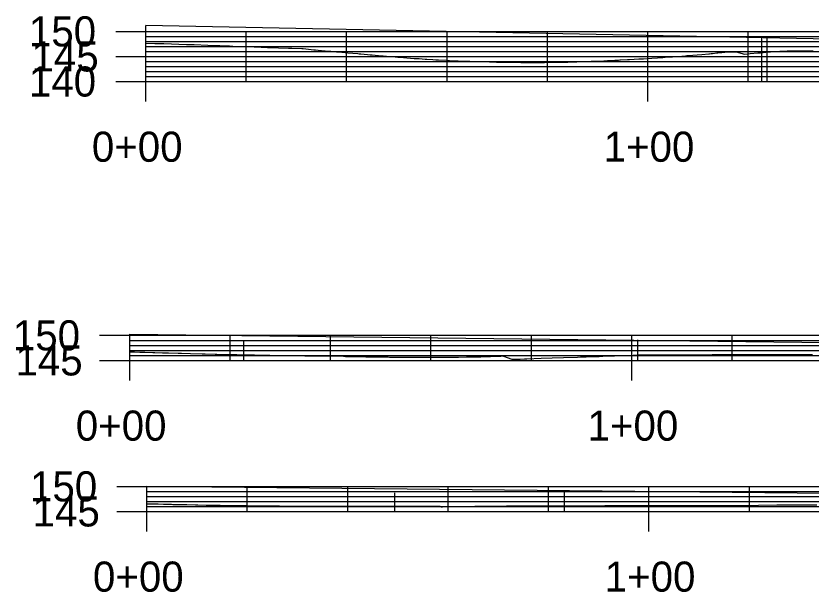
# Model space of a CAD drawing. Extents: x 1556849 to 1559393, y 1802592 to 1804749.
# Drawn here: x 1559135.3 to 1559293.7, y 1802770.9 to 1802885.8 of the extents above; entities that cross this region are included whole.
import ezdxf

# ---------------------------------------------------------------- set-up
doc = ezdxf.new("R2010")
doc.units = 0
for name, color, linetype in [('R_Axis', 7, 'Continuous'), ('R_Axis Annot', 7, 'Continuous'), ('R_Fin Surface', 7, 'Continuous'), ('R_Grid', 7, 'Continuous'), ('R_Proposed Const Limits_Hand', 7, 'Continuous'), ('R_Vert Alg Annot', 7, 'Continuous')]:
    doc.layers.add(name, color=color, linetype=linetype)

msp = doc.modelspace()

# ---------------------------------------------------------------- linework, layer by layer
at = {"layer": 'R_Axis'}
for p, q in [((1559161.2, 1802872.74), (1559161.2, 1802882.74)), ((1559161.2, 1802872.74), (1559361.2, 1802872.74)), ((1559158, 1802817.13), (1559158, 1802822.13)), ((1559158, 1802817.13), (1559358, 1802817.13)), ((1559161.42, 1802787.02), (1559161.42, 1802792.02)), ((1559161.42, 1802787.02), (1559361.42, 1802787.02))]:
    msp.add_line(p, q, dxfattribs=at)
at = {"layer": 'R_Fin Surface'}
for points in [[(1559161.2, 1802880.39), (1559163.01, 1802880.33), (1559164.76, 1802880.29), (1559169.29, 1802880.15), (1559170.23, 1802880.12), (1559170.8, 1802880.1), (1559173.55, 1802880.01), (1559175.33, 1802879.95), (1559175.37, 1802879.95), (1559175.67, 1802879.93), (1559175.96, 1802879.92), (1559177.86, 1802879.85), (1559178.53, 1802879.82), (1559180.34, 1802879.75), (1559180.47, 1802879.74), (1559180.68, 1802879.74), (1559181.6, 1802879.7), (1559182.79, 1802879.65), (1559184.18, 1802879.6), (1559185.22, 1802879.56), (1559185.43, 1802879.55), (1559185.55, 1802879.55), (1559187.04, 1802879.49), (1559187.61, 1802879.47), (1559189.64, 1802879.4), (1559189.98, 1802879.38), (1559190.27, 1802879.37), (1559190.31, 1802879.37), (1559192.3, 1802879.3), (1559192.32, 1802879.3), (1559192.53, 1802879.3), (1559194.64, 1802879.08), (1559194.7, 1802879.08), (1559194.97, 1802879.05), (1559195.51, 1802879), (1559196.93, 1802878.87), (1559198.03, 1802878.77), (1559199.21, 1802878.66), (1559199.41, 1802878.64), (1559199.54, 1802878.63), (1559200.89, 1802878.51), (1559201.46, 1802878.46), (1559203.43, 1802878.3), (1559203.7, 1802878.27), (1559204.01, 1802878.25), (1559204.03, 1802878.25), (1559205.35, 1802878.14), (1559205.92, 1802878.09), (1559206.29, 1802878.05), (1559208.13, 1802877.88), (1559208.3, 1802877.87), (1559208.46, 1802877.85), (1559209.89, 1802877.73), (1559210.32, 1802877.7), (1559211.39, 1802877.61), (1559212.5, 1802877.52), (1559212.55, 1802877.52), (1559212.84, 1802877.5), (1559213.22, 1802877.47), (1559214.67, 1802877.36), (1559215.63, 1802877.3), (1559216.83, 1802877.22), (1559217.02, 1802877.21), (1559217.17, 1802877.2), (1559218.38, 1802877.13), (1559218.98, 1802877.09), (1559219.51, 1802877.06), (1559221.12, 1802876.97), (1559221.18, 1802876.97), (1559221.47, 1802876.96), (1559221.7, 1802876.95), (1559223.26, 1802876.87), (1559223.39, 1802876.87), (1559225.39, 1802876.78), (1559225.39, 1802876.78), (1559225.58, 1802876.78), (1559225.74, 1802876.77), (1559225.74, 1802876.77), (1559226.9, 1802876.74), (1559227.53, 1802876.73), (1559229.65, 1802876.67), (1559229.66, 1802876.67), (1559230.01, 1802876.66), (1559230.29, 1802876.65), (1559231.07, 1802876.63), (1559231.07, 1802876.63), (1559231.77, 1802876.62), (1559231.77, 1802876.62), (1559231.95, 1802876.61), (1559233.85, 1802876.58), (1559233.89, 1802876.58), (1559234.24, 1802876.57), (1559234.25, 1802876.57), (1559235.91, 1802876.55), (1559236.01, 1802876.55), (1559237.92, 1802876.54), (1559238.14, 1802876.54), (1559238.47, 1802876.54), (1559238.51, 1802876.54), (1559239.42, 1802876.54), (1559239.57, 1802876.54), (1559239.67, 1802876.54), (1559240.27, 1802876.54), (1559240.62, 1802876.55), (1559242.4, 1802876.57), (1559242.49, 1802876.57), (1559242.77, 1802876.58), (1559243.22, 1802876.59), (1559244.54, 1802876.61), (1559245.23, 1802876.63), (1559246.68, 1802876.67), (1559246.83, 1802876.67), (1559247.06, 1802876.68), (1559247.81, 1802876.7), (1559248.83, 1802876.73), (1559249.91, 1802876.77), (1559250.99, 1802876.82), (1559251.21, 1802876.82), (1559251.38, 1802876.83), (1559252.45, 1802876.88), (1559253.16, 1802876.91), (1559254.65, 1802876.98), (1559255.34, 1802877.01), (1559255.63, 1802877.03), (1559255.74, 1802877.03), (1559257.14, 1802877.11), (1559257.53, 1802877.13), (1559259.43, 1802877.23), (1559259.74, 1802877.25), (1559260.11, 1802877.27), (1559260.15, 1802877.28), (1559260.35, 1802877.29), (1559261.96, 1802877.39), (1559263.11, 1802877.47), (1559264.05, 1802877.53), (1559264.2, 1802877.54), (1559264.58, 1802877.57), (1559264.62, 1802877.57), (1559266.08, 1802877.68), (1559266.45, 1802877.7), (1559267.96, 1802877.82), (1559268.73, 1802877.88), (1559268.99, 1802877.9), (1559269.17, 1802877.92), (1559270.13, 1802878), (1559271.02, 1802878.07), (1559271.94, 1802878.15), (1559273.34, 1802878.28), (1559273.48, 1802878.29), (1559273.8, 1802878.32), (1559274.1, 1802878.35), (1559274.97, 1802878.43), (1559275.11, 1802878.44), (1559275.68, 1802878.5), (1559275.96, 1802878.53), (1559277.23, 1802878.67), (1559277.23, 1802878.67), (1559277.23, 1802878.67), (1559277.94, 1802878.68), (1559278.05, 1802878.68), (1559278.29, 1802878.68), (1559278.81, 1802878.69), (1559280.44, 1802878.2), (1559281.59, 1802878.3), (1559283.1, 1802878.43), (1559283.27, 1802878.44), (1559283.63, 1802878.47), (1559284.73, 1802878.57), (1559287.51, 1802878.81), (1559288.27, 1802878.82), (1559288.96, 1802878.83), (1559291.04, 1802878.86), (1559293.32, 1802878.89), (1559294.14, 1802878.89)], [(1559158, 1802818.86), (1559158.93, 1802818.83), (1559159.99, 1802818.8), (1559161.03, 1802818.77), (1559162.57, 1802818.73), (1559162.7, 1802818.72), (1559162.97, 1802818.71), (1559164.53, 1802818.67), (1559165.11, 1802818.65), (1559165.69, 1802818.64), (1559167.62, 1802818.58), (1559167.96, 1802818.57), (1559168.02, 1802818.57), (1559168.31, 1802818.57), (1559170.11, 1802818.52), (1559172.45, 1802818.46), (1559172.57, 1802818.45), (1559172.57, 1802818.45), (1559172.97, 1802818.44), (1559173.02, 1802818.44), (1559175, 1802818.39), (1559175.34, 1802818.38), (1559177.41, 1802818.33), (1559177.51, 1802818.33), (1559177.81, 1802818.32), (1559178.15, 1802818.31), (1559179.09, 1802818.29), (1559179.32, 1802818.28), (1559179.8, 1802818.27), (1559180.71, 1802818.25), (1559182.17, 1802818.22), (1559182.35, 1802818.22), (1559182.56, 1802818.21), (1559182.71, 1802818.21), (1559182.87, 1802818.21), (1559183.3, 1802818.2), (1559183.74, 1802818.19), (1559184.15, 1802818.19), (1559184.52, 1802818.18), (1559185.93, 1802818.16), (1559186.85, 1802818.14), (1559187.11, 1802818.14), (1559187.24, 1802818.14), (1559188.61, 1802818.12), (1559189.16, 1802818.11), (1559191, 1802818.09), (1559191.46, 1802818.08), (1559191.79, 1802818.08), (1559191.86, 1802818.08), (1559192.85, 1802818.07), (1559193.01, 1802818.07), (1559193.67, 1802818.06), (1559193.75, 1802818.06), (1559193.98, 1802818.06), (1559196.03, 1802818.04), (1559196.04, 1802818.04), (1559196.43, 1802818.04), (1559196.49, 1802818.04), (1559197.79, 1802818.03), (1559198.29, 1802818.02), (1559198.35, 1802818.01), (1559200.55, 1802817.95), (1559200.59, 1802817.95), (1559200.95, 1802817.94), (1559201.23, 1802817.94), (1559202.79, 1802817.9), (1559203.35, 1802817.89), (1559205.04, 1802817.86), (1559205.16, 1802817.86), (1559205.44, 1802817.85), (1559206.13, 1802817.84), (1559207.27, 1802817.83), (1559208.36, 1802817.82), (1559209.5, 1802817.81), (1559209.72, 1802817.8), (1559209.91, 1802817.8), (1559211.04, 1802817.79), (1559211.73, 1802817.79), (1559213.4, 1802817.78), (1559213.95, 1802817.77), (1559214.28, 1802817.77), (1559214.37, 1802817.77), (1559215.99, 1802817.77), (1559216.18, 1802817.77), (1559217.65, 1802817.78), (1559218.4, 1802817.77), (1559218.41, 1802817.77), (1559218.83, 1802817.77), (1559218.89, 1802817.77), (1559220.63, 1802817.78), (1559220.8, 1802817.78), (1559222.86, 1802817.79), (1559222.91, 1802817.79), (1559223.29, 1802817.8), (1559223.5, 1802817.8), (1559225.09, 1802817.82), (1559225.39, 1802817.83), (1559227.33, 1802817.86), (1559227.39, 1802817.86), (1559227.77, 1802817.87), (1559227.93, 1802817.87), (1559228.89, 1802817.89), (1559228.99, 1802817.9), (1559229.57, 1802817.92), (1559229.84, 1802817.93), (1559231.83, 1802818), (1559231.92, 1802817.99), (1559232.32, 1802818.01), (1559232.43, 1802817.97), (1559232.43, 1802817.97), (1559234.09, 1802817.35), (1559235.78, 1802817.41), (1559236.61, 1802817.44), (1559236.93, 1802817.45), (1559237.11, 1802817.45), (1559239.95, 1802817.55), (1559242.16, 1802817.63), (1559244.38, 1802817.7), (1559247.21, 1802817.8), (1559247.79, 1802817.82), (1559248.91, 1802817.85), (1559251.49, 1802817.94), (1559252.25, 1802817.97), (1559256.97, 1802818.13), (1559257.3, 1802818.14), (1559259.19, 1802818.21), (1559261.54, 1802818.22), (1559262.35, 1802818.23), (1559265.31, 1802818.23), (1559267.39, 1802818.24), (1559269.07, 1802818.25), (1559272.44, 1802818.27), (1559272.83, 1802818.27), (1559273.99, 1802818.28), (1559277.26, 1802818.29), (1559277.48, 1802818.29), (1559277.74, 1802818.29), (1559282.53, 1802818.3), (1559286.71, 1802818.31), (1559287.58, 1802818.32), (1559287.77, 1802818.32), (1559288.59, 1802818.32), (1559289.14, 1802818.32), (1559291.28, 1802818.33), (1559291.28, 1802818.33), (1559291.29, 1802818.33), (1559292.29, 1802818.33), (1559292.62, 1802818.33), (1559293.99, 1802818.33)], [(1559161.42, 1802788.56), (1559161.53, 1802788.55), (1559162.22, 1802788.53), (1559162.89, 1802788.52), (1559163.24, 1802788.51), (1559163.65, 1802788.5), (1559164.69, 1802788.48), (1559166.16, 1802788.44), (1559166.32, 1802788.44), (1559166.58, 1802788.43), (1559166.8, 1802788.43), (1559166.91, 1802788.42), (1559167.53, 1802788.41), (1559167.83, 1802788.4), (1559168.4, 1802788.39), (1559168.65, 1802788.38), (1559169.34, 1802788.37), (1559171.12, 1802788.33), (1559171.21, 1802788.33), (1559171.54, 1802788.32), (1559173.21, 1802788.29), (1559173.56, 1802788.28), (1559173.93, 1802788.27), (1559175.98, 1802788.24), (1559176.36, 1802788.23), (1559176.4, 1802788.23), (1559177.53, 1802788.22), (1559177.61, 1802788.22), (1559177.66, 1802788.21), (1559178.39, 1802788.2), (1559178.49, 1802788.2), (1559180.4, 1802788.18), (1559180.75, 1802788.17), (1559180.78, 1802788.17), (1559181.18, 1802788.17), (1559181.2, 1802788.17), (1559182.98, 1802788.15), (1559183.15, 1802788.15), (1559183.39, 1802788.15), (1559185.51, 1802788.13), (1559185.58, 1802788.13), (1559185.93, 1802788.12), (1559187.43, 1802788.11), (1559187.85, 1802788.11), (1559189.54, 1802788.1), (1559190.18, 1802788.1), (1559190.48, 1802788.09), (1559190.61, 1802788.09), (1559191.21, 1802788.09), (1559192.51, 1802788.09), (1559193.96, 1802788.08), (1559194.82, 1802788.08), (1559195.08, 1802788.08), (1559195.25, 1802788.08), (1559196.34, 1802788.07), (1559197.12, 1802788.07), (1559198.15, 1802788.07), (1559199.42, 1802788.06), (1559199.65, 1802788.06), (1559199.85, 1802788.06), (1559200.74, 1802788.06), (1559201.72, 1802788.06), (1559202.87, 1802788.06), (1559204.01, 1802788.05), (1559204.23, 1802788.05), (1559204.44, 1802788.05), (1559205.34, 1802788.05), (1559206.29, 1802788.05), (1559207.49, 1802788.05), (1559208.58, 1802788.05), (1559208.79, 1802788.05), (1559209.02, 1802788.05), (1559209.9, 1802788.05), (1559210.86, 1802788.05), (1559212.05, 1802788.05), (1559213.15, 1802788.05), (1559213.38, 1802788.05), (1559213.6, 1802788.05), (1559214.18, 1802788.05), (1559214.74, 1802788.05), (1559215.09, 1802788.05), (1559215.44, 1802788.05), (1559216.56, 1802788.06), (1559217.73, 1802788.06), (1559219.68, 1802788.06), (1559219.75, 1802788.07), (1559220.03, 1802787.96), (1559220.29, 1802787.96), (1559222.53, 1802788.01), (1559222.57, 1802788.01), (1559223.04, 1802788.02), (1559223.32, 1802788.02), (1559226.74, 1802788.09), (1559227.84, 1802788.09), (1559228.05, 1802788.09), (1559232.04, 1802788.1), (1559233.07, 1802788.11), (1559234.27, 1802788.11), (1559234.76, 1802788.11), (1559236.79, 1802788.12), (1559238.08, 1802788.12), (1559240.44, 1802788.13), (1559243.1, 1802788.14), (1559244.64, 1802788.15), (1559248.11, 1802788.15), (1559248.85, 1802788.15), (1559252.65, 1802788.17), (1559253.11, 1802788.17), (1559253.13, 1802788.17), (1559257.94, 1802788.17), (1559258.14, 1802788.18), (1559262.76, 1802788.18), (1559263.16, 1802788.18), (1559263.58, 1802788.18), (1559268.17, 1802788.19), (1559272.42, 1802788.2), (1559273.19, 1802788.2), (1559273.35, 1802788.2), (1559274.19, 1802788.2), (1559274.64, 1802788.2), (1559276.87, 1802788.2), (1559276.87, 1802788.2), (1559276.88, 1802788.2), (1559277.94, 1802788.21), (1559278.2, 1802788.21), (1559279.23, 1802788.21), (1559283.22, 1802788.26), (1559286.9, 1802788.3), (1559288.23, 1802788.3), (1559291.73, 1802788.34), (1559293.25, 1802788.34), (1559294.88, 1802788.34)]]:
    msp.add_lwpolyline(points, dxfattribs=at)
at = {"layer": 'R_Grid'}
for p, q in [((1559155.2, 1802882.74), (1559161.2, 1802882.74)), ((1559155.2, 1802882.74), (1559161.2, 1802882.74)), ((1559161.2, 1802882.74), (1559361.2, 1802882.74)), ((1559161.2, 1802882.74), (1559361.2, 1802882.74)), ((1559181.2, 1802872.74), (1559181.2, 1802882.74)), ((1559201.2, 1802872.74), (1559201.2, 1802882.74)), ((1559221.2, 1802872.74), (1559221.2, 1802882.74)), ((1559241.2, 1802872.74), (1559241.2, 1802882.74)), ((1559261.2, 1802872.74), (1559261.2, 1802882.74)), ((1559281.2, 1802872.74), (1559281.2, 1802882.74)), ((1559161.2, 1802881.74), (1559164.2, 1802881.74)), ((1559161.2, 1802881.74), (1559361.2, 1802881.74)), ((1559161.2, 1802880.74), (1559164.2, 1802880.74)), ((1559161.2, 1802880.74), (1559361.2, 1802880.74)), ((1559161.2, 1802879.74), (1559164.2, 1802879.74)), ((1559161.2, 1802879.74), (1559361.2, 1802879.74)), ((1559161.2, 1802878.74), (1559164.2, 1802878.74)), ((1559161.2, 1802878.74), (1559361.2, 1802878.74)), ((1559155.2, 1802877.74), (1559161.2, 1802877.74)), ((1559161.2, 1802877.74), (1559361.2, 1802877.74)), ((1559161.2, 1802876.74), (1559164.2, 1802876.74)), ((1559161.2, 1802876.74), (1559361.2, 1802876.74)), ((1559161.2, 1802875.74), (1559164.2, 1802875.74)), ((1559161.2, 1802875.74), (1559361.2, 1802875.74)), ((1559161.2, 1802874.74), (1559164.2, 1802874.74)), ((1559161.2, 1802874.74), (1559361.2, 1802874.74)), ((1559161.2, 1802873.74), (1559164.2, 1802873.74)), ((1559161.2, 1802873.74), (1559361.2, 1802873.74)), ((1559155.2, 1802872.74), (1559161.2, 1802872.74)), ((1559161.2, 1802868.74), (1559161.2, 1802872.74)), ((1559261.2, 1802868.74), (1559261.2, 1802872.74)), ((1559152, 1802822.13), (1559158, 1802822.13)), ((1559152, 1802822.13), (1559158, 1802822.13)), ((1559158, 1802822.13), (1559358, 1802822.13)), ((1559158, 1802822.13), (1559358, 1802822.13)), ((1559158, 1802821.13), (1559161, 1802821.13)), ((1559158, 1802821.13), (1559358, 1802821.13)), ((1559178, 1802817.13), (1559178, 1802822.13)), ((1559198, 1802817.13), (1559198, 1802822.13)), ((1559218, 1802817.13), (1559218, 1802822.13)), ((1559238, 1802817.13), (1559238, 1802822.13)), ((1559258, 1802817.13), (1559258, 1802822.13)), ((1559278, 1802817.13), (1559278, 1802822.13)), ((1559158, 1802820.13), (1559161, 1802820.13)), ((1559158, 1802820.13), (1559358, 1802820.13)), ((1559158, 1802819.13), (1559161, 1802819.13)), ((1559158, 1802819.13), (1559358, 1802819.13)), ((1559158, 1802818.13), (1559161, 1802818.13)), ((1559158, 1802818.13), (1559358, 1802818.13)), ((1559152, 1802817.13), (1559158, 1802817.13)), ((1559158, 1802813.13), (1559158, 1802817.13)), ((1559258, 1802813.13), (1559258, 1802817.13)), ((1559155.42, 1802792.02), (1559161.42, 1802792.02)), ((1559155.42, 1802792.02), (1559161.42, 1802792.02)), ((1559161.42, 1802792.02), (1559361.42, 1802792.02)), ((1559161.42, 1802792.02), (1559361.42, 1802792.02)), ((1559161.42, 1802791.02), (1559164.42, 1802791.02)), ((1559161.42, 1802791.02), (1559361.42, 1802791.02)), ((1559181.42, 1802787.02), (1559181.42, 1802792.02)), ((1559201.42, 1802787.02), (1559201.42, 1802792.02)), ((1559221.42, 1802787.02), (1559221.42, 1802792.02)), ((1559241.42, 1802787.02), (1559241.42, 1802792.02)), ((1559261.42, 1802787.02), (1559261.42, 1802792.02)), ((1559281.42, 1802787.02), (1559281.42, 1802792.02)), ((1559161.42, 1802790.02), (1559164.42, 1802790.02)), ((1559161.42, 1802790.02), (1559361.42, 1802790.02)), ((1559161.42, 1802789.02), (1559164.42, 1802789.02)), ((1559161.42, 1802789.02), (1559361.42, 1802789.02)), ((1559161.42, 1802788.02), (1559164.42, 1802788.02)), ((1559161.42, 1802788.02), (1559361.42, 1802788.02)), ((1559155.42, 1802787.02), (1559161.42, 1802787.02)), ((1559161.42, 1802783.02), (1559161.42, 1802787.02)), ((1559261.42, 1802783.02), (1559261.42, 1802787.02))]:
    msp.add_line(p, q, dxfattribs=at)
at = {"layer": 'R_Proposed Const Limits_Hand'}
for p, q in [((1559161.2, 1802880.39), (1559161.2, 1802883.89)), ((1559307.85, 1802880.97), (1559161.2, 1802883.89)), ((1559283.88, 1802872.74), (1559283.88, 1802881.5)), ((1559284.98, 1802872.83), (1559284.98, 1802881.59)), ((1559161.2, 1802872.74), (1559283.88, 1802872.74)), ((1559158, 1802818.86), (1559158, 1802822.36)), ((1559158, 1802822.36), (1559314, 1802820.5)), ((1559180.71, 1802817.13), (1559180.71, 1802820.92)), ((1559259.19, 1802817.13), (1559259.19, 1802821.21)), ((1559158, 1802817.13), (1559180.71, 1802817.13)), ((1559158, 1802817.13), (1559259.19, 1802817.13)), ((1559161.42, 1802788.56), (1559161.42, 1802792.06)), ((1559161.42, 1802792.06), (1559317.42, 1802790.46)), ((1559244.6, 1802787.02), (1559244.6, 1802791.15)), ((1559210.81, 1802787.02), (1559210.81, 1802790.72)), ((1559161.42, 1802787.02), (1559210.81, 1802787.02)), ((1559161.42, 1802787.02), (1559244.6, 1802787.02))]:
    msp.add_line(p, q, dxfattribs=at)

# ---------------------------------------------------------------- texts
at = {"layer": 'R_Axis'}
for s, p in [('150', (1559137.91, 1802879.74)), ('150', (1559137.91, 1802879.74)), ('145', (1559138.43, 1802874.74)), ('140', (1559137.91, 1802869.74)), ('150', (1559134.71, 1802819.13)), ('150', (1559134.71, 1802819.13)), ('145', (1559135.23, 1802814.13)), ('150', (1559138.13, 1802789.02)), ('150', (1559138.13, 1802789.02)), ('145', (1559138.65, 1802784.02))]:
    msp.add_text(s, height=6, dxfattribs=at).set_placement(p)
at = {"layer": 'R_Axis Annot'}
for p in [(1559161.2, 1802872.74), (1559158, 1802817.13), (1559161.42, 1802787.02)]:
    msp.add_text('-', height=0.0001, dxfattribs=at).set_placement(p)
at = {"layer": 'R_Vert Alg Annot'}
for s, p in [('0+00', (1559150.45, 1802856.74)), ('1+00', (1559252.39, 1802856.74)), ('0+00', (1559147.25, 1802801.13)), ('1+00', (1559249.19, 1802801.13)), ('0+00', (1559150.67, 1802771.02)), ('1+00', (1559252.61, 1802771.02))]:
    msp.add_text(s, height=6, dxfattribs=at).set_placement(p)

doc.saveas('drawing.dxf')
